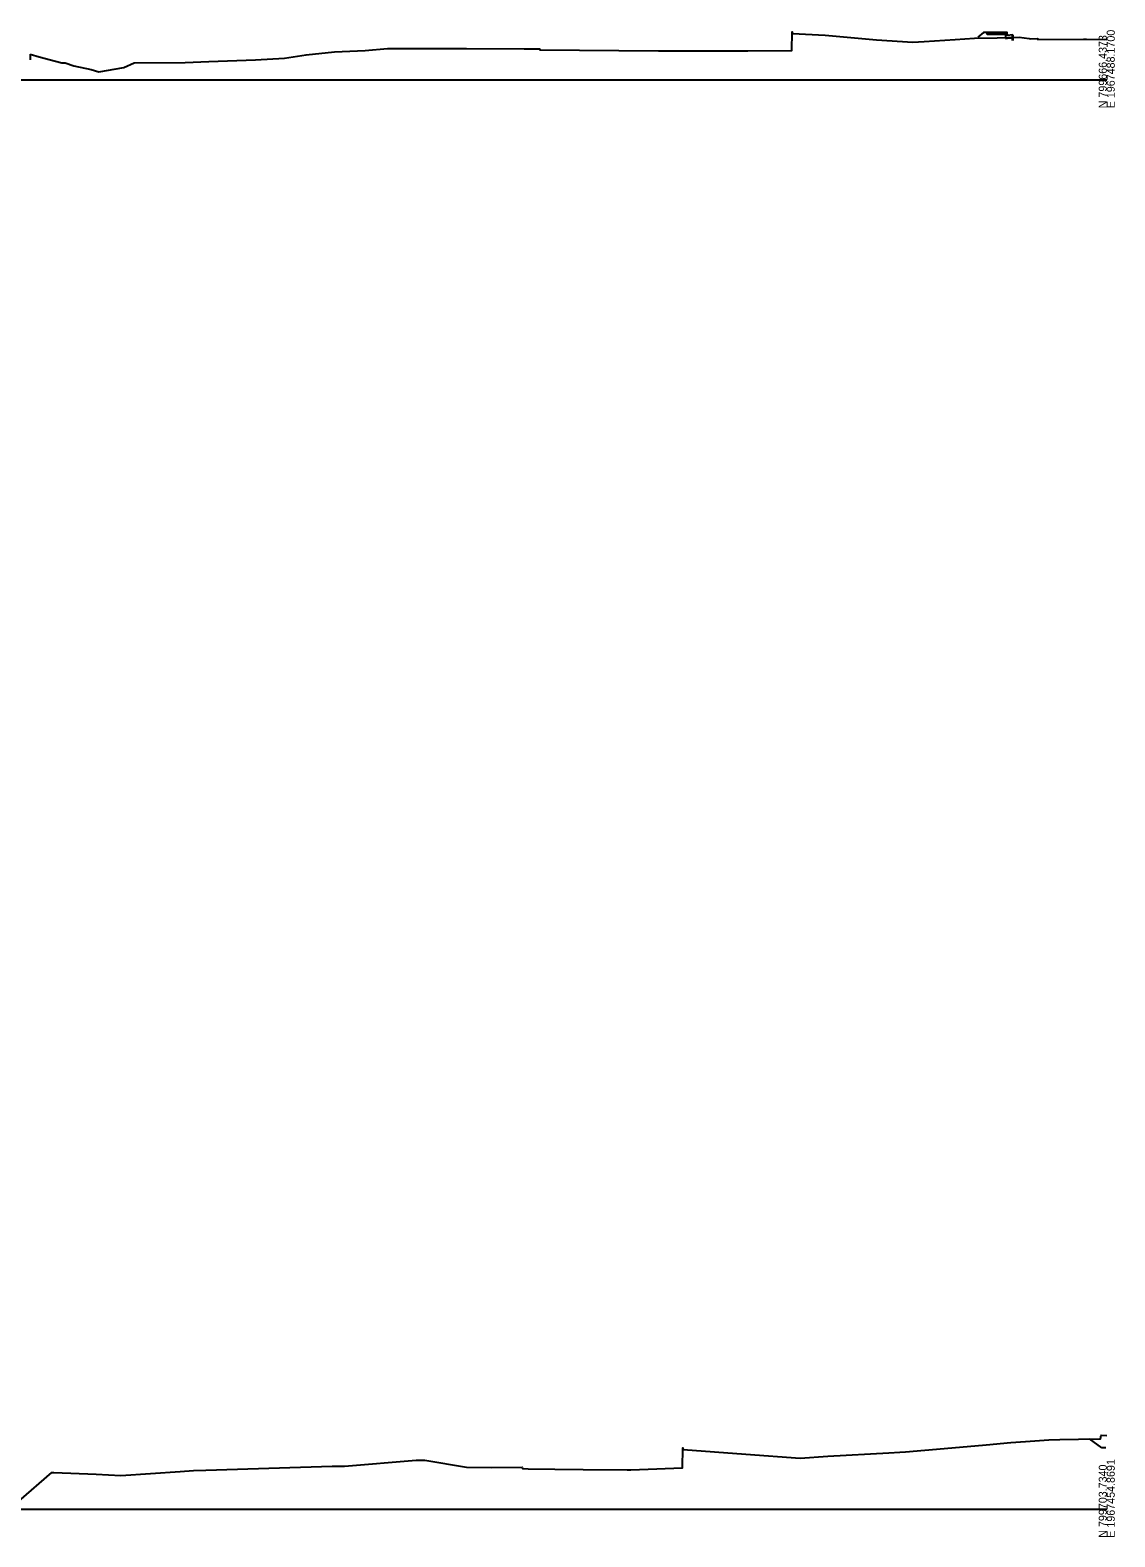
# Model space of a CAD drawing. Extents: x 1017 to 19997, y -1947 to 50737.
# Drawn here: x 14823 to 15203, y 11990 to 12517 of the extents above; entities that cross this region are included whole.
import ezdxf

# ---------------------------------------------------------------- set-up
doc = ezdxf.new("R2010")
doc.units = 0
for name, color, linetype in [('RD_GPK_XS_Cell', 7, 'Continuous'), ('RD_XS_Base', 7, 'Continuous'), ('RD_XS_CurbBase', 7, 'Continuous'), ('RD_XS_ExGround', 7, 'Continuous'), ('RD_XS_ExPaveRet', 7, 'Continuous'), ('RD_XS_Greenside', 7, 'Continuous'), ('RD_XS_Pave', 7, 'Continuous'), ('RD_XS_PaveOvlay', 7, 'Continuous'), ('RD_XS_SW', 7, 'Continuous'), ('RD_XS_SWbase', 7, 'Continuous'), ('RD_XS_TieSlope', 7, 'Continuous')]:
    doc.layers.add(name, color=color, linetype=linetype)

msp = doc.modelspace()

# ---------------------------------------------------------------- linework, layer by layer
at = {"layer": 'RD_GPK_XS_Cell'}
for p, q in [((14600, 12500), (15200, 12500)), ((14600, 12000), (15200, 12000))]:
    msp.add_line(p, q, dxfattribs=at)
at = {"layer": 'RD_XS_Base'}
for points in [[(15167.08, 12513.77), (15167.08, 12515.11)], [(15167.2, 12513.78), (15167.08, 12513.77)], [(15167.2, 12515.12), (15167.2, 12513.78)]]:
    msp.add_lwpolyline(points, dxfattribs=at)
at = {"layer": 'RD_XS_CurbBase'}
for points in [[(15167.08, 12515.7), (15165.28, 12515.48), (15165.17, 12516.48), (15164.53, 12516.46)], [(15164.53, 12516.46), (15164.53, 12514.46)], [(15164.53, 12514.46), (15165.28, 12514.48), (15167.08, 12514.7)], [(15167.08, 12514.7), (15167.08, 12515.7)]]:
    msp.add_lwpolyline(points, dxfattribs=at)
at = {"layer": 'RD_XS_ExGround'}
for points in [[(14823.4, 12508.9), (14826.57, 12508.03), (14832.24, 12506.54), (14834.54, 12505.89), (14835.64, 12505.86), (14838.67, 12504.9), (14844.78, 12503.53), (14847.43, 12502.78), (14856.18, 12504.23), (14859.74, 12505.94), (14877.69, 12505.99), (14885.96, 12506.31), (14902.28, 12506.94), (14912.38, 12507.59), (14919.92, 12508.69), (14929.89, 12509.75), (14940.63, 12510.23), (14948.38, 12510.91), (14976.04, 12510.97), (14996.25, 12510.82), (15001.61, 12510.79), (15001.73, 12510.44), (15043.15, 12510.05), (15043.95, 12510.04), (15061.59, 12510.08), (15074.43, 12510.09), (15089.83, 12510.18), (15089.99, 12516.73), (15090.11, 12516.12), (15101.47, 12515.57), (15119.45, 12513.98), (15132.19, 12513.08), (15136.16, 12513.36), (15146.98, 12514.1), (15153.75, 12514.49), (15161.66, 12514.6), (15169.38, 12514.91), (15172.87, 12514.41), (15173.29, 12514.31), (15175.83, 12514.38), (15175.87, 12514.08), (15191.92, 12514.18), (15192.95, 12514.17), (15200, 12514.09)], [(14819.45, 12002.79), (14830.96, 12012.84), (14831.69, 12012.8), (14846.48, 12012.29), (14855.12, 12011.73), (14875.89, 12013.15), (14880.58, 12013.54), (14884.89, 12013.65), (14917.96, 12014.67), (14929.02, 12014.98), (14933.31, 12015.07), (14958.45, 12017.13), (14961.44, 12017.08), (14976.05, 12014.68), (14984.71, 12014.52), (14995.47, 12014.67), (14995.6, 12014.17), (14997.6, 12014.12), (15006.97, 12013.97), (15016.9, 12013.84), (15032.19, 12013.78), (15033.49, 12013.79), (15036.5, 12013.9), (15051.56, 12014.42), (15051.73, 12021.48), (15051.85, 12020.87), (15073.8, 12019.22), (15092.72, 12017.89), (15102.47, 12018.56), (15123.78, 12019.71), (15127.68, 12019.93), (15129.59, 12020.02), (15143.14, 12021.25), (15157.81, 12022.49), (15166.4, 12023.26), (15171.59, 12023.72), (15179.7, 12024.21), (15183.63, 12024.39), (15190.11, 12024.46), (15197.85, 12024.65), (15198.01, 12025.86), (15200, 12025.73)]]:
    msp.add_lwpolyline(points, dxfattribs=at)
at = {"layer": 'RD_XS_ExPaveRet'}
msp.add_line((14823.4, 12508.9), (14823.4, 12506.9), dxfattribs=at)
at = {"layer": 'RD_XS_Greenside'}
for points in [[(15158.18, 12516.48), (15156.91, 12516.49)], [(15199.66, 12021.4), (15198.32, 12021.4)]]:
    msp.add_lwpolyline(points, dxfattribs=at)
at = {"layer": 'RD_XS_Pave'}
for points in [[(15167.08, 12515.42), (15167.2, 12515.43)], [(15167.08, 12515.11), (15167.08, 12515.42)], [(15167.2, 12515.12), (15167.08, 12515.11)], [(15167.2, 12515.43), (15167.2, 12515.12)]]:
    msp.add_lwpolyline(points, dxfattribs=at)
at = {"layer": 'RD_XS_PaveOvlay'}
for points in [[(15167.08, 12515.74), (15167.2, 12515.75)], [(15167.08, 12515.74), (15167.2, 12515.75)], [(15167.08, 12515.42), (15167.08, 12515.7), (15167.08, 12515.74)], [(15167.2, 12515.75), (15167.2, 12515.43)]]:
    msp.add_lwpolyline(points, dxfattribs=at)
at = {"layer": 'RD_XS_SW'}
msp.add_lwpolyline([(15164.53, 12516.46), (15158.18, 12516.48)], dxfattribs=at)
at = {"layer": 'RD_XS_SWbase'}
for points in [[(15158.18, 12515.82), (15158.18, 12516.48)], [(15164.53, 12515.8), (15158.18, 12515.82)], [(15164.53, 12516.46), (15164.53, 12515.8)]]:
    msp.add_lwpolyline(points, dxfattribs=at)
at = {"layer": 'RD_XS_TieSlope'}
for points in [[(15156.91, 12516.49), (15154.96, 12514.9)], [(15198.32, 12021.4), (15193.96, 12024.61)]]:
    msp.add_lwpolyline(points, dxfattribs=at)

# ---------------------------------------------------------------- texts
at = {"layer": 'RD_GPK_XS_Cell'}
for s, p in [('E 1967488.1700', (15202.8, 12490)), ('N 799666.4373', (15200, 12490)), ('E 1967454.8691', (15202.8, 11990)), ('N 799703.7340', (15200, 11990))]:
    msp.add_text(s, height=2.8, rotation=90, dxfattribs=at).set_placement(p)

doc.saveas('drawing.dxf')
